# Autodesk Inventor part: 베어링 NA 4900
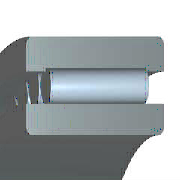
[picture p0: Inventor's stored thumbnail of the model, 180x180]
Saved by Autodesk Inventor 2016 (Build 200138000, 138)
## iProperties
Created: 2009-02
Part Number: 베어링 NA 4900
Material: 스테인리스강
Description: 니들 롤러 베어링 - 경계 치수 및 공차
Document SubType Name: Modeling
Standard: KS B 2029
Designer: SeoGD™
Standards Organization: KS
Language: ko-KR
Size Designation: NA 4900 - 10 x 22 x 13
Categories: <MemberInstance><Categories><Category DisplayName="샤프트 부품" InternalName="7f7aeb1f-a693-4053-b835-cee3144e0d98" Mnemonic="SHFT"><Category DisplayName="베어링" Inter
Density: 8.08 g/cm^3
Mass: 24.488 g
Surface Area: 38.613 cm^2
Volume: 3.0307 cm^3
Appearance: 반광택
IsCustomPart: 0
Author: SeoGD™
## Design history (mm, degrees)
sketch "스케치"
  geometry: L1 (1.857, 9)-(11.143, 9); L2 (11.143, 9)-(11.143, 7); L3 (13, 7)-(0, 7); L4 (1.857, 7)-(1.857, 9); L5 (1.857, 8)-(11.143, 8); L6 (6.5, 8)-(6.5, 7); L7 (0, 5)-(13, 5); L8 (0, 11)-(13, 11); L9 (13, 5)-(13, 7); L10 (13, 8.8)-(13, 11); L11 (1.857, 8.8)-(0, 8.8); L12 (11.143, 8.8)-(13, 8.8); L13 (-6, 0)-(36, 0) reference; L14 (0, -1.9)-(0, 14.9) reference
  constraints: 24 end point, 8 point on line, 3 midpoint, 3 parallel, 3 perpendicular, 2 symmetric about line, 1 horizontal, 1 other
  dimensions: "d6" = 10 diameter of L7 L13 (= WD); "d7" = 14 diameter of L3 L13 (= KID1); "d8" = 22 diameter of L8 L13 (= BD); "d9" = 16 diameter of L6.start L13 (= 0.5 x WD + 0.5 x BD); "d10" = 17.6 diameter of L12 L13 (= 0.9 x BD + 0.9 x WD - 0.8 x KID1); "d11" = 18 diameter of L1 L13 (= BD + WD - KID1); "d12" = 1.85714 distance between parallel lines of L14 L4 (= 0.142857 x KB); "d13" = 13 distance between parallel lines of L14 L9 (= KB); "d14" = 11.14286 distance between parallel lines of L14 L2 (= 0.857143 x KB)
revolve "본체" stored, may be unused: angle "d17" = 90 deg
revolve "롤러" stored, may be unused: angle "d18" = 90 deg
pattern_circular "IDS_ARRAYROLLER[SIMPL:T]" dims angle "d2" = 360 deg
body "Solid1"
fillet "모깎기1" dims "d0" = 0.3 (= KRS)
other parameters: "WD" = 10 [user parameter; used in 6 equation terms], "BD" = 22 [user parameter; used in 6 equation terms], "KB" = 13 [user parameter; used in 3 equation terms], "KID1" = 14 [user parameter; used in 4 equation terms], "KRS" = 0.3 [user parameter; used in 1 equation term], "d3" = 0, "d4" = 0, "d5" = 0, "d15" = 0, "d16" = 0, "BC0" = 9150000 [user parameter], "WR" = 5 (= 0.5 x WD) [user parameter], "BBA" = 0 [user parameter], "BC" = 8150000 [user parameter], "BR" = 11 (= 0.5 x BD) [user parameter]
